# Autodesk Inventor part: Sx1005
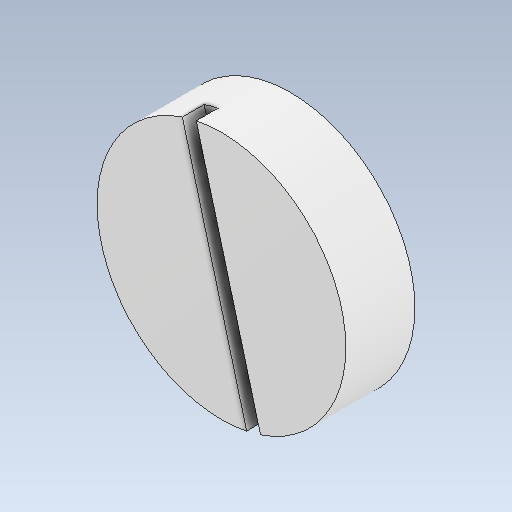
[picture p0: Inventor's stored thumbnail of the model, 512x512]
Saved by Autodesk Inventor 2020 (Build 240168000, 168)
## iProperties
Created: 2021-02
Part Number: Sx1005
Material: Generico
Document SubType Name: Modeling
Designer: zambolin
Density: 1 g/cm^3
Appearance: Default
Author: zambolin
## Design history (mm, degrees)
feature "Solido2"
node "Solido1"
